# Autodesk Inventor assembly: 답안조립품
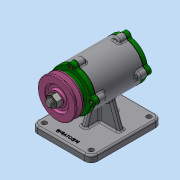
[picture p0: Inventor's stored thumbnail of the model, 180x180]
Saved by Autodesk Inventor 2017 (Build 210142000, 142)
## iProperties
Part Number: 답안조립품
Material: 일반
Document SubType Name: Assembly
Designer: MRC
Author: MRC
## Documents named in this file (12)
- C:\Users\MRC\Desktop\720716V1003\답안조립품.iam
- C:\Users\MRC\Desktop\720716V1003\본체.ipt
- C:\Users\MRC\Desktop\720716V1003\V-벨트풀리.ipt
- C:\Users\MRC\Desktop\720716V1003\개스킷.ipt
- C:\Users\MRC\Desktop\720716V1003\너트 M12 x 1.25.ipt
- C:\Users\MRC\Desktop\720716V1003\뒤커버.ipt
- C:\Users\MRC\Desktop\720716V1003\베어링 6204.ipt
- C:\Users\MRC\Desktop\720716V1003\볼트 M4 x 12.ipt
- C:\Users\MRC\Desktop\720716V1003\앞커버.ipt
- C:\Users\MRC\Desktop\720716V1003\오일 실.ipt
- C:\Users\MRC\Desktop\720716V1003\축.ipt
- C:\Users\MRC\Desktop\720716V1003\키 4 x 4.ipt
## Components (3 placed, 2 different names)
1. V-벨트풀리:1
2. 개스킷:1
3. 개스킷:2
